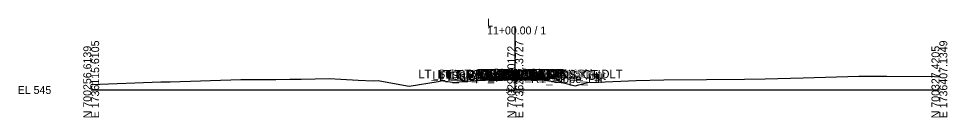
# Model space of a CAD drawing. Extents: x -26 to 697, y -10 to 2642.
# Drawn here: x -25.7 to 302.8, y 390.3 to 425.2 of the extents above; entities that cross this region are included whole.
import ezdxf

# ---------------------------------------------------------------- set-up
doc = ezdxf.new("R2010")
doc.units = 0
for name, color, linetype in [('Default', 7, 'Continuous'), ('Exist Cross Section Cell', 7, 'Continuous'), ('Exist XS Center Line Elevation Label', 7, 'Continuous'), ('Exist XS Ground Line', 7, 'Continuous'), ('Prop CMT Pvmt Course 1', 7, 'Continuous'), ('Prop CMT Pvmt Course 2', 7, 'Continuous'), ('Prop CMT Pvmt Surface', 7, 'Continuous'), ('Prop CMT Pvmt Surface Shoulder', 7, 'Continuous'), ('Prop CMT Shld Paved Course 1', 7, 'Continuous'), ('Prop CMT Shld Paved Course 2', 7, 'Continuous'), ('Prop CMT Slope Grass', 7, 'Continuous'), ('Prop CMT Subgrade Earthwork', 7, 'Continuous'), ('Prop XS SE Text', 7, 'Continuous'), ('Prop XS Side Slope Text', 7, 'Continuous'), ('Scratch_Level_1', 7, 'Continuous')]:
    doc.layers.add(name, color=color, linetype=linetype)

msp = doc.modelspace()

# ---------------------------------------------------------------- linework, layer by layer
at = {"layer": 'Exist Cross Section Cell'}
for p, q in [((150, 400), (150, 422.44)), ((0, 400), (150, 400)), ((150, 400), (300, 400))]:
    msp.add_line(p, q, dxfattribs=at)
at = {"layer": 'Exist XS Ground Line'}
msp.add_lwpolyline([(0, 401.98), (24.64, 402.84), (26.58, 402.92), (27.96, 402.93), (52.91, 403.66), (53.34, 403.66), (65.35, 403.72), (70.22, 403.81), (74.22, 403.88), (84.17, 404.03), (88.33, 403.8), (94.39, 403.42), (99.77, 403.29), (101.49, 403.32), (107.84, 402.23), (112.46, 401.39), (122.75, 403.02), (124.23, 403.3), (124.59, 403.26), (128.5, 402.62), (130.17, 402.91), (131.17, 403.05), (135.93, 403.3), (140.21, 403.55), (142.52, 403.59), (149.79, 403.72), (157.36, 403.6), (159.81, 403.54), (161.84, 403.23), (167.1, 402.48), (170.68, 401.61), (171.23, 401.49), (172.52, 401.82), (175.61, 402.61), (179.08, 402.72), (192.69, 403.35), (202.58, 403.56), (217.59, 403.67), (231.08, 403.88), (238.41, 403.98), (251.81, 404.34), (271.54, 404.91), (275.52, 404.88), (281.43, 404.89), (298.28, 404.78), (300, 404.69)], dxfattribs=at)
at = {"layer": 'Prop CMT Pvmt Course 1'}
for points in [[(150, 404.48), (139, 404.27)], [(139, 404.27), (139, 404.06)], [(139, 404.06), (150, 404.27)], [(150, 404.27), (150, 404.48)], [(150, 404.48), (161, 404.26)], [(150, 404.27), (150, 404.48)], [(161, 404.05), (150, 404.27)], [(161, 404.26), (161, 404.05)]]:
    msp.add_lwpolyline(points, dxfattribs=at)
msp.add_lwpolyline([(150, 404.27), (150, 404.37), (150, 404.37), (150, 404.27)], close=True, dxfattribs=at)
msp.add_lwpolyline([(150, 404.27), (150, 404.37), (150, 404.37), (150, 404.27)], close=True, dxfattribs=at)
at = {"layer": 'Prop CMT Pvmt Course 2'}
for points in [[(150, 404.27), (139, 404.06)], [(150, 403.81), (150, 404.27)], [(150, 403.81), (150, 404.27)], [(150, 404.27), (161, 404.05)], [(139, 404.06), (139, 403.6)], [(139, 403.6), (150, 403.81)], [(161, 403.59), (150, 403.81)], [(161, 404.05), (161, 403.59)]]:
    msp.add_lwpolyline(points, dxfattribs=at)
at = {"layer": 'Prop CMT Pvmt Surface'}
for points in [[(150, 404.48), (139, 404.27)], [(150, 404.48), (161, 404.26)]]:
    msp.add_lwpolyline(points, dxfattribs=at)
at = {"layer": 'Prop CMT Pvmt Surface Shoulder'}
for points in [[(139, 404.27), (138.99, 404.27)], [(161, 404.26), (161.01, 404.26)]]:
    msp.add_lwpolyline(points, dxfattribs=at)
at = {"layer": 'Prop CMT Shld Paved Course 1'}
for points in [[(139, 404.27), (138.99, 404.27), (138.78, 404.05)], [(139, 404.06), (139, 404.27)], [(161, 404.26), (161.01, 404.26), (161.22, 404.04)], [(161, 404.05), (161, 404.26)], [(138.78, 404.05), (139, 404.06)], [(161.22, 404.04), (161, 404.05)]]:
    msp.add_lwpolyline(points, dxfattribs=at)
at = {"layer": 'Prop CMT Shld Paved Course 2'}
for points in [[(139, 404.06), (138.78, 404.05), (138.77, 404.05), (138.3, 403.59)], [(138.3, 403.59), (139, 403.6)], [(139, 403.6), (139, 404.06)], [(161, 404.05), (161.22, 404.04), (161.23, 404.04), (161.7, 403.58)], [(161, 403.59), (161, 404.05)], [(161.7, 403.58), (161, 403.59)]]:
    msp.add_lwpolyline(points, dxfattribs=at)
at = {"layer": 'Prop CMT Slope Grass'}
for points in [[(138.99, 404.27), (136, 404.03), (134.38, 403.22)], [(161.01, 404.26), (164, 404.02), (167.08, 402.48)]]:
    msp.add_lwpolyline(points, dxfattribs=at)
at = {"layer": 'Prop CMT Subgrade Earthwork'}
for points in [[(138.3, 403.59), (137.72, 404.17)], [(161.7, 403.58), (162.28, 404.16)], [(139, 403.6), (138.3, 403.59)], [(150, 403.81), (139, 403.6)], [(150, 403.81), (161, 403.59)], [(161, 403.59), (161.7, 403.58)]]:
    msp.add_lwpolyline(points, dxfattribs=at)
at = {"layer": 'Scratch_Level_1'}
for p, q in [((150, 404.27), (139, 404.06)), ((139.01, 403.94), (150, 404.15)), ((161, 404.05), (150, 404.27)), ((150, 404.27), (150.01, 404.15)), ((150.01, 404.15), (160.99, 403.93)), ((139, 404.06), (139, 403.94)), ((161, 403.93), (161, 404.05))]:
    msp.add_line(p, q, dxfattribs=at)
for points in [[(150, 404.15), (150, 404.15), (150, 404.27)], [(139, 403.94), (139.01, 403.94)], [(160.99, 403.93), (161, 403.93)]]:
    msp.add_lwpolyline(points, dxfattribs=at)

# ---------------------------------------------------------------- texts
at = {"layer": 'Default'}
for s, height, p in [('RT_PV1_OEEOP', 3, (136.36, 404.37)), ('LT_PV1_OEEOP', 3, (136.54, 404.37)), ('RT_PV1_IEEOP', 3, (137.5, 404.37)), ('LT_PV1_IEEOP', 3, (137.68, 404.37)), ('PV1_PGL', 3, (142.41, 404.48)), ('LT_Sub_Trench_Out_DLT', 3, (115.67, 404.17)), ('LT_Sub_Trench_Out', 3, (120.63, 403.59)), ('LT_GS_OS_CTL', 3, (122.39, 404.03)), ('LT_PS2_Shelf_Out', 3, (122.74, 404.05)), ('LT_Slope_Fill', 3, (123.09, 403.22)), ('LT_PS2_OEOP', 3, (126.14, 404.05)), ('LT_PV2_OEOT', 3, (126.24, 404.06)), ('LT_Sub_OEOT', 3, (126.31, 403.6)), ('LT_PV1_OEOT', 3, (126.6, 404.27)), ('LT_PS1_OEOP', 3, (126.71, 404.27)), ('RT_PV2_OEEOP', 3, (136, 404.27)), ('RT_Sub_OEEOP', 3, (136.07, 403.81)), ('LT_PV2_OEEOP', 3, (136.18, 404.27)), ('LT_Sub_OEEOP', 3, (136.25, 403.81)), ('RT_PV2_IEEOP', 3, (137.14, 404.27)), ('LT_PV2_IEEOP', 3, (137.32, 404.27)), ('RT_Sub_Trench_Out_DLT', 3, (140.05, 404.16)), ('PV2_PGL', 3, (142.05, 404.27)), ('RT_Sub_Trench_Out', 3, (143.85, 403.58)), ('RT_PS2_Shelf_Out', 3, (145.03, 404.04)), ('RT_PV2_OEOT', 3, (148.06, 404.05)), ('RT_Sub_OEOT', 3, (148.13, 403.59)), ('RT_PS2_OEOP', 3, (148.4, 404.04)), ('RT_PV1_OEOT', 3, (148.42, 404.26)), ('RT_PS1_OEOP', 3, (148.55, 404.26)), ('RT_GS_OS_CTL', 3, (150.21, 404.02)), ('RT_Slope_Fill', 3, (155.61, 402.48)), ('-', 0.0001, (0, 400))]:
    msp.add_text(s, height=height, dxfattribs=at).set_placement(p)
at = {"layer": 'Exist Cross Section Cell'}
for s, p in [('L', (140, 422.44)), ('11+00.00 / 1', (140, 419.64)), ('EL 545', (-26, 398.6))]:
    msp.add_text(s, height=2.8, dxfattribs=at).set_placement(p)
for s, p in [('E 1736115.6105', (2.8, 390)), ('E 1736261.3727', (152.8, 390)), ('E 1736407.1349', (302.8, 390)), ('N 700256.6139', (0, 390)), ('N 700292.0172', (150, 390)), ('N 700327.4205', (300, 390))]:
    msp.add_text(s, height=2.8, rotation=90, dxfattribs=at).set_placement(p)
at = {"layer": 'Exist XS Center Line Elevation Label'}
msp.add_text('548.72', height=1.6, dxfattribs=at).set_placement((146.63, 398.92))
at = {"layer": 'Prop XS SE Text'}
for s, rotation, p in [('0.019', 1.098, (141.25, 405.31)), ('0.020', 358.8542, (152.02, 405.44))]:
    msp.add_text(s, height=2, rotation=rotation, dxfattribs=at).set_placement(p)
at = {"layer": 'Prop XS Side Slope Text'}
for rotation, p in [(26.5651, (133.43, 403.59)), (333.4349, (164.46, 404.63))]:
    msp.add_text('2:1', height=2, rotation=rotation, dxfattribs=at).set_placement(p)

doc.saveas('drawing.dxf')
